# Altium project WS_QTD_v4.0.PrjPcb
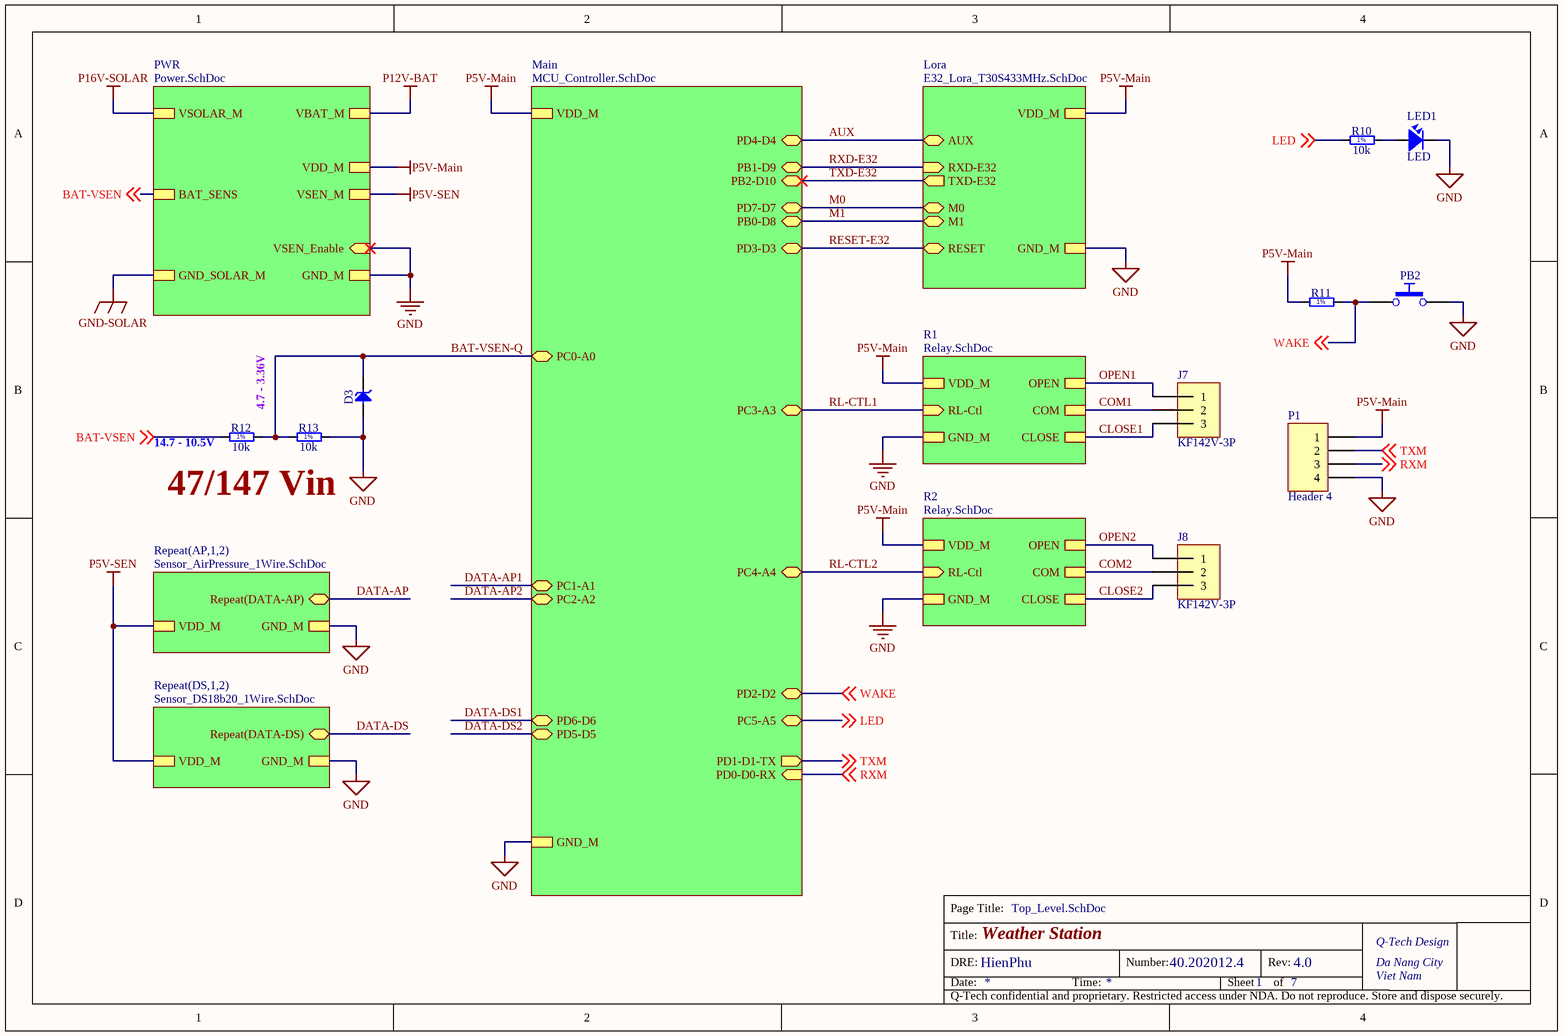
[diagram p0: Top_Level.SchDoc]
DocNumber: 40.202012.4; DRE: HienPhu; ProjectParameterName: Weather Station; Rev: 4.0
7 sheets, 75 parts. Net scope: strictly hierarchical (ports join the sheet entries above them; power ports are local).
Board file: Pcb_WS_v4.PcbDoc
Sheets:
  Top_Level.SchDoc
    Main = MCU_Controller.SchDoc
    Lora = E32_Lora_T30S433MHz.SchDoc
    PWR = Power.SchDoc
    AP1 = Sensor_AirPressure_1Wire.SchDoc
    AP2 = Sensor_AirPressure_1Wire.SchDoc
    DS1 = Sensor_DS18b20_1Wire.SchDoc
    DS2 = Sensor_DS18b20_1Wire.SchDoc
    R1 = Relay.SchDoc
    R2 = Relay.SchDoc

## Sheet Top_Level.SchDoc
size A4; Organization: Q-Tech Design; Address1: Da Nang City; Address2: Viet Nam; DocumentNumber: 1; SheetNumber: 1; SheetTotal: 7

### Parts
D3  BZV55-B5V1  [DIOMELF3515N]  (value not drawn)
J7  KF142V-3P  [CON KF142V-3P-5.08]
J8  KF142V-3P  [CON KF142V-3P-5.08]
LED1  LED  [L-0805]
P1  Header 4  [HDR1X4]
PB2  Push Button  [PB_TYCO_FSMSM]  (value not drawn)
R10  10k  [RESC1608X55N]
R11  10k  [RESC1608X55N]  (value not drawn)
R12  10k  [RESC1608X55N]
R13  10k  [RESC1608X55N]

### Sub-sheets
Lora = E32_Lora_T30S433MHz.SchDoc: M0 (bidir), M1 (bidir), RESET (bidir), AUX (bidir), GND_M, VDD_M, RXD-E32 (in), TXD-E32 (out)
Main = MCU_Controller.SchDoc: PB1-D9 (bidir), PB2-D10 (bidir), GND_M, PC3-A3 (bidir), PB0-D8 (bidir), PD6-D6 (bidir), PD2-D2 (bidir), PC4-A4 (bidir), PD4-D4 (bidir), PC5-A5 (bidir), PC2-A2 (bidir), PD0-D0-RX (in), PD3-D3 (bidir), PC1-A1 (bidir), PD7-D7 (bidir), VDD_M, PD5-D5 (bidir), PC0-A0 (bidir), PD1-D1-TX (out)
PWR = Power.SchDoc: VSOLAR_M, VSEN_Enable (in), BAT_SENS, VSEN_M, GND_SOLAR_M, VBAT_M, GND_M, VDD_M
R1 = Relay.SchDoc: OPEN, GND_M, CLOSE, RL-Ctl (in), VDD_M, COM
R2 = Relay.SchDoc: OPEN, GND_M, CLOSE, RL-Ctl (in), VDD_M, COM
Repeat(AP,1,2) = Sensor_AirPressure_1Wire.SchDoc: VDD_M, GND_M, Repeat(DATA-AP) (bidir)
Repeat(DS,1,2) = Sensor_DS18b20_1Wire.SchDoc: GND_M, Repeat(DATA-DS) (bidir), VDD_M

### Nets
GND: D3.2(A) LED1.2 P1.4 PB2.2 R13.2 ; sheet Main/GND_M, sheet Lora/GND_M, sheet PWR/VSEN_Enable, sheet PWR/GND_M, sheet Repeat(AP,1,2)/GND_M, sheet Repeat(DS,1,2)/GND_M, sheet R1/GND_M, sheet R2/GND_M
P5V-Main: P1.1 R11.1 ; sheet Main/VDD_M, sheet Lora/VDD_M, sheet PWR/VDD_M, sheet R1/VDD_M, sheet R2/VDD_M
P5V-SEN: sheet PWR/VSEN_M, sheet Repeat(AP,1,2)/VDD_M, sheet Repeat(DS,1,2)/VDD_M
AUX: sheet Main/PD4-D4, sheet Lora/AUX
BAT-VSEN: R12.1 ; off-sheet BAT-VSEN, sheet PWR/BAT_SENS
BAT-VSEN-Q: D3.1(C) R12.2 R13.1 ; sheet Main/PC0-A0
CLOSE1: J7.3 ; sheet R1/CLOSE
CLOSE2: J8.3 ; sheet R2/CLOSE
COM1: J7.2 ; sheet R1/COM
COM2: J8.2 ; sheet R2/COM
LED: R10.1 ; off-sheet LED, sheet Main/PC5-A5
M0: sheet Main/PD7-D7, sheet Lora/M0
M1: sheet Main/PB0-D8, sheet Lora/M1
OPEN1: J7.1 ; sheet R1/OPEN
OPEN2: J8.1 ; sheet R2/OPEN
RESET-E32: sheet Main/PD3-D3, sheet Lora/RESET
RL-CTL1: sheet Main/PC3-A3, sheet R1/RL-Ctl
RL-CTL2: sheet Main/PC4-A4, sheet R2/RL-Ctl
RXD-E32: sheet Main/PB1-D9, sheet Lora/RXD-E32
RXM: P1.3 ; off-sheet RXM, sheet Main/PD0-D0-RX
TXD-E32: sheet Main/PB2-D10, sheet Lora/TXD-E32
TXM: P1.2 ; off-sheet TXM, sheet Main/PD1-D1-TX
WAKE: PB2.1 R11.2 ; off-sheet WAKE, sheet Main/PD2-D2
NetLED1_1: LED1.1 R10.2

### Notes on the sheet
- (near R12) 14.7 - 10.5V
- 4.7 - 3.36V
- 47/147 Vin

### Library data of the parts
D3 = BZV55-B5V1: Zener Diode; Part Description: Voltage Regulator Diode; Manufacturer: NXP SEMICONDUCTORS; Voltage: 5V1; Power: 500mW; Table: Diodes
J7 J8 = CON KF142V-3P-5.08
LED1 = LED: LED Single colour Green and Red; Value: LED 3 ly Single Colour
P1 = Header 4: Header, 4-Pin
PB2 = PB SPST 1NO-2NO: Push-Button Switch SPDT; Part Description: 12VDC 50mA SPST Tactile  Push-Button Switch; Manufacturer: TYCO ELECTRONICS; Manufacturer Part Number: FSMSM or 1437566-3; Table: Switches
R10 = R0603_200R_1%_0.1W_100PPM: Resistor - 1%; Part Description: General Purpose Thick Film Chip Resistor; Manufacturer: GENERIC; Manufacturer1 Part Number: NRC06F2000TRF; Value: 200; Power: 0.1W; TC: ±100ppm/°C; Table: Resistors SMD
R11 = R0603_10K_1%_0.1W_100PPM: Resistor - 1%; Part Description: General Purpose Thick Film Chip Resistor; Manufacturer: GENERIC; Manufacturer1 Part Number: NRC06F1002TRF; Power: 0.1W; TC: ±100ppm/°C; Table: Resistors SMD
R12 = R0603_2M_1%_0.1W_100PPM: Resistor - 1%; Part Description: General Purpose Thick Film Chip Resistor; Manufacturer: GENERIC; Manufacturer1 Part Number: NRC06F2004TRF; Value: 2M; Power: 0.1W; TC: ±100ppm/°C; Table: Resistors SMD
R13 = R0603_1M_1%_0.1W_100PPM: Resistor - 1%; Part Description: General Purpose Thick Film Chip Resistor; Manufacturer: GENERIC; Manufacturer1 Part Number: NRC06F1004TRF; Value: 1M; Power: 0.1W; TC: ±100ppm/°C; Table: Resistors SMD

## Sheet MCU_Controller.SchDoc
size A4; Organization: Q-Tech Design; Address1: Da Nang City; Address2: Viet Nam; DocumentNumber: 2; SheetNumber: 2; SheetTotal: 7
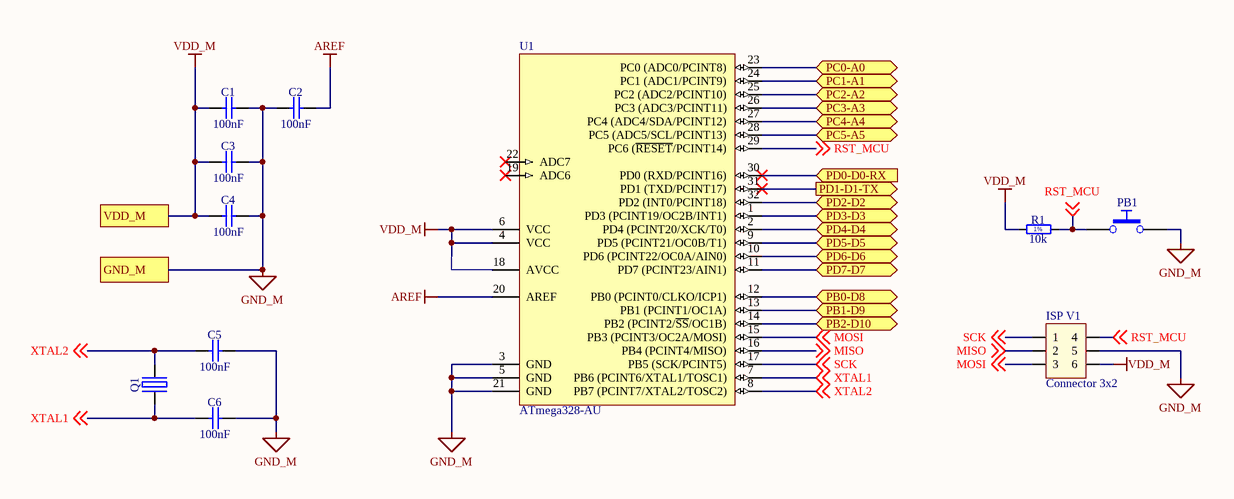
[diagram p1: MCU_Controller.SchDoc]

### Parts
C1  100nF  [CAPC1608X87N]
C2  100nF  [CAPC1608X87N]
C3  100nF  [CAPC1608X87N]
C4  100nF  [CAPC1608X87N]
C5  100nF  [CAPC1608X87N]
C6  100nF  [CAPC1608X87N]
ISP_V1  Connector 3x2  [JP3x2]
PB1  Push Button  [PB_TYCO_FSMSM]  (value not drawn)
Q1  20MHz  [XTAL_HC-49/U]  (value not drawn)
R1  10k  [RESC1608X55N]
U1  ATmega328-AU  [32A_ATM-M]

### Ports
GND_M, PB0-D8 (bidir), PB1-D9 (bidir), PB2-D10 (bidir), PC0-A0 (bidir), PC1-A1 (bidir), PC2-A2 (bidir), PC3-A3 (bidir), PC4-A4 (bidir), PC5-A5 (bidir), PD0-D0-RX (in), PD1-D1-TX (out), PD2-D2 (bidir), PD3-D3 (bidir), PD4-D4 (bidir), PD5-D5 (bidir), PD6-D6 (bidir), PD7-D7 (bidir), VDD_M

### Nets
AREF: C2.2 U1.20(AREF)
GND_M: C1.2 C2.1 C3.2 C4.2 C5.2 C6.2 ISP_V1.5 PB1.2 U1.3(GND) U1.5(GND) U1.21(GND) ; port GND_M  [project net GND]
VDD_M: C1.1 C3.1 C4.1 ISP_V1.6 R1.1 U1.4(VCC) U1.6(VCC) U1.18(AVCC) ; port VDD_M  [project net P5V-Main]
AUX: U1.2(PD4_(PCINT20/XCK/T0)) ; port PD4-D4
BAT-VSEN-Q: U1.23(PC0_(ADC0/PCINT8)) ; port PC0-A0
DATA-AP1: U1.24(PC1_(ADC1/PCINT9)) ; port PC1-A1
DATA-AP2: U1.25(PC2_(ADC2/PCINT10)) ; port PC2-A2
DATA-DS1: U1.10(PD6_(PCINT22/OC0A/AIN0)) ; port PD6-D6
DATA-DS2: U1.9(PD5_(PCINT21/OC0B/T1)) ; port PD5-D5
LED: U1.28(PC5_(ADC5/SCL/PCINT13)) ; port PC5-A5
M0: U1.11(PD7_(PCINT23/AIN1)) ; port PD7-D7
M1: U1.12(PB0_(PCINT0/CLKO/ICP1)) ; port PB0-D8
MISO: ISP_V1.2 U1.16(PB4_(PCINT4/MISO)) ; off-sheet MISO
MOSI: ISP_V1.3 U1.15(PB3_(PCINT3/OC2A/MOSI)) ; off-sheet MOSI
RESET-E32: U1.1(PD3_(PCINT19/OC2B/INT1)) ; port PD3-D3
RL-CTL1: U1.26(PC3_(ADC3/PCINT11)) ; port PC3-A3
RL-CTL2: U1.27(PC4_(ADC4/SDA/PCINT12)) ; port PC4-A4
RST_MCU: ISP_V1.4 PB1.1 R1.2 U1.29(PC6_(~{RESET}/PCINT14)) ; off-sheet RST_MCU
RXD-E32: U1.13(PB1_(PCINT1/OC1A)) ; port PB1-D9
RXM: U1.30(PD0_(RXD/PCINT16)) ; port PD0-D0-RX
SCK: ISP_V1.1 U1.17(PB5_(SCK/PCINT5)) ; off-sheet SCK
TXD-E32: U1.14(PB2_(PCINT2/~{SS}/OC1B)) ; port PB2-D10
TXM: U1.31(PD1_(TXD/PCINT17)) ; port PD1-D1-TX
WAKE: U1.32(PD2_(INT0/PCINT18)) ; port PD2-D2
XTAL1: C6.1 Q1.1(OSC1) U1.7(PB6_(PCINT6/XTAL1/TOSC1)) ; off-sheet XTAL1
XTAL2: C5.1 Q1.2(OSC2) U1.8(PB7_(PCINT7/XTAL2/TOSC2)) ; off-sheet XTAL2

Not connected (* = marked no-connect by the designer): U1 19(ADC6)* 22(ADC7)*

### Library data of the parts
C1-C4 = CC0603_100NF_50V_10%_X7R: Non-polarised capacitor; Part Description: SMD Multilayer Chip Ceramic Capacitor; Manufacturer: GENERIC; Manufacturer1 Part Number: 223858615649; Voltage: 50V; TC: X7R; Tolerance: ±10%; Table: Capacitors SMD
C5 C6 = CC0603_22PF_50V_5%_NP0: Non-polarised capacitor; Part Description: SMD Multilayer Chip Ceramic Capacitor; Manufacturer: GENERIC; Manufacturer1 Part Number: 223886715229; Value: 22pF; Voltage: 50V; TC: NP0; Tolerance: ±5%; Table: Capacitors SMD
ISP_V1 = JP3x2
PB1 = PB SPST 1NO-2NO: as PB2 on sheet Top_Level
Q1 = XTAL_20MHZ_AEL_HC-49/U: Quartz Crystal; Part Description: ±30ppm Quartz Crystal Resonator, HC-49/U Type; Manufacturer: AEL CRYSTALS; Manufacturer Part Number: X20M000000L010; Table: Crystals & Oscillators
R1 = R0603_10K_1%_0.1W_100PPM: as R11 on sheet Top_Level
U1 = ATmega328-AU: 8-bit AVR Microcontroller, 32KB Flash, 1KB EEPROM, 2KB SRAM, 32-pin TQFP, Industrial Grade (-40°C to 85°C)

## Sheet E32_Lora_T30S433MHz.SchDoc
size A4; Organization: Q-Tech Design; Address1: Da Nang City; Address2: Viet Nam; DocumentNumber: 3; SheetNumber: 3; SheetTotal: 7
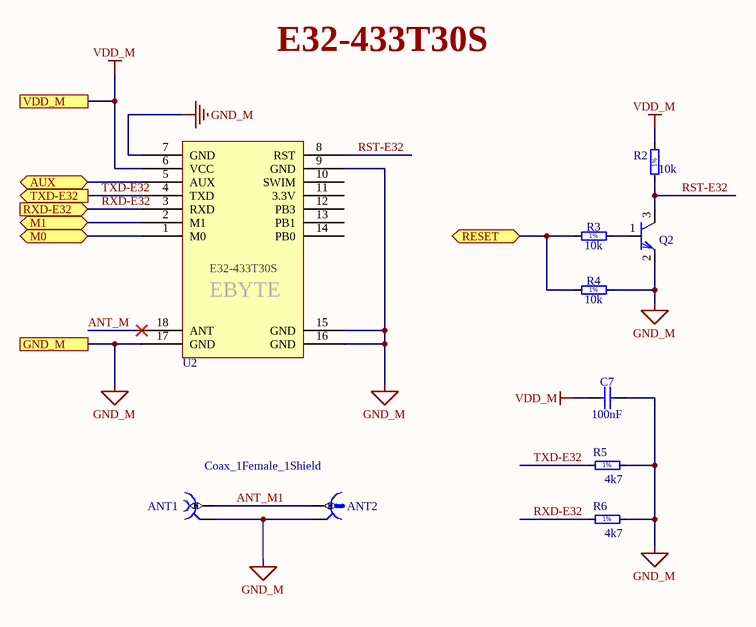
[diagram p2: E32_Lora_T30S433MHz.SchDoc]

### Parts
ANT1  Coax_1Female_1Shield  [HUBER-SUHNER_85 SMA-50-0-101/111 NE]
ANT2  U.FL  [HIROSE_U.FL-R-SMT-1(10)]  (value not drawn)
C7  100nF  [CAPC1608X87N]
Q2  C1815  [SOT23-3]  (value not drawn)
R2  10k  [RESC1608X55N]
R3  10k  [RESC1608X55N]
R4  10k  [RESC1608X55N]
R5  4k7  [RESC1608X55N]
R6  4k7  [RESC1608X55N]
U2  E32-T30S  [E32-T30S]  (value not drawn)

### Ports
AUX (bidir), GND_M, M0 (bidir), M1 (bidir), RESET (bidir), RXD-E32 (in), TXD-E32 (out), VDD_M

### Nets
GND_M: ANT1.2 ANT2.2 C7.2 Q2.2(E) R4.1 R5.2 R6.2 U2.7(GND) U2.9(GND) U2.15(GND) U2.16(GND) U2.17(GND) ; port GND_M  [project net GND]
VDD_M: C7.1 R2.2 U2.6(VCC) ; port VDD_M  [project net P5V-Main]
ANT_M: U2.18(ANT)
ANT_M1: ANT1.1 ANT2.1
AUX: U2.5(AUX) ; port AUX
M0: U2.1(M0) ; port M0
M1: U2.2(M1) ; port M1
RESET-E32: R3.1 R4.2 ; port RESET
RST-E32: Q2.3(C) R2.1 U2.8(RST)
RXD-E32: R6.1 U2.3(RXD) ; port RXD-E32
TXD-E32: R5.1 U2.4(TXD) ; port TXD-E32
NetQ2_1: Q2.1(B) R3.2

Not connected (* = marked no-connect by the designer): U2 10(SWIM) 11(3.3V) 12(PB3) 13(PB1) 14(PB0)

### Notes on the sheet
- E32-433T30S

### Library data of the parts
ANT1 = HUBER-SUHNER_85_SMA-50-0-101/111_NE: Part Description: SMA 50 Ohms Right Angle PCB Jack; Manufacturer: HUBER+SUHNER; Table: Miscellaneous
ANT2 = HIROSE_U.FL-R-SMT-1(10): Part Description: Up to 6GHz Ultra Small Surface Mount Male Coaxial Connectors U.FL Series; Manufacturer: HIROSE (HRS); Table: Miscellaneous
C7 = CC0603_100NF_50V_10%_X7R: as C1 on sheet MCU_Controller
Q2 = 2SC1815: PSpiceTemplate: Q^@REFDES %c %b %e @MODEL; Vendor: Digikey
R2 = R0603_4K7_1%_0.1W_100PPM: Resistor - 1%; Part Description: General Purpose Thick Film Chip Resistor; Manufacturer: GENERIC; Manufacturer1 Part Number: NRC06F4701TRF; Value: 4k7; Power: 0.1W; TC: ±100ppm/°C; Table: Resistors SMD
R3 R4 = R0603_1K_1%_0.1W_100PPM: Resistor - 1%; Part Description: General Purpose Thick Film Chip Resistor; Manufacturer: GENERIC; Manufacturer1 Part Number: NRC06F1001TRF; Value: 1k; Power: 0.1W; TC: ±100ppm/°C; Table: Resistors SMD
R5 R6 = R0603_10K_1%_0.1W_100PPM: Resistor - 1%; Part Description: General Purpose Thick Film Chip Resistor; Manufacturer: GENERIC; Manufacturer1 Part Number: NRC06F1002TRF; Value: 10k; Power: 0.1W; TC: ±100ppm/°C; Table: Resistors SMD
U2 = E32-433T30S: Lora Ebyte E32-T30S Module

## Sheet Power.SchDoc
size A4; Organization: Q-Tech Design; Address1: Da Nang City; Address2: Viet Nam; DocumentNumber: 7; SheetNumber: 7; SheetTotal: 7
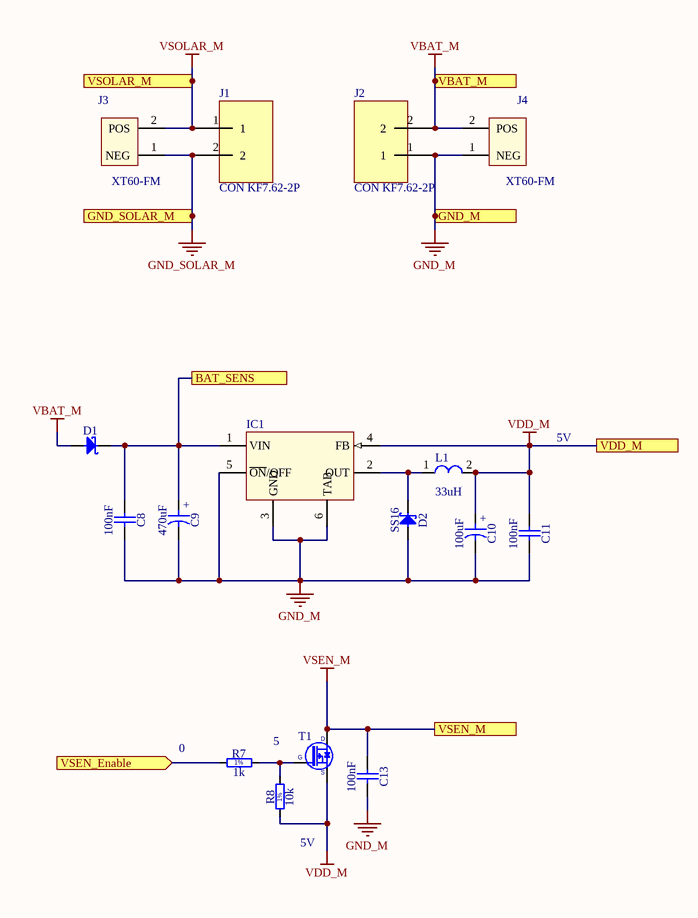
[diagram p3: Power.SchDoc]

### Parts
C8  100nF  [CAPC1608X87N]
C9  470uF  [CAPAE1030X1020N]
C10  100uF  [CAPMP6032X280N]
C11  100nF  [CAPC1608X87N]
C13  100nF  [CAPC1608X87N]
D1  SS16  [DIOM5127X229N]  (value not drawn)
D2  SS16  [DIOM5127X229N]
IC1  LM2596  [TO263-5]  (value not drawn)
J1  CON KF7.62-2P  [CON KF7.62-2P]
J2  CON KF7.62-2P  [CON KF7.62-2P]
J3  XT60-FM  [XT60-FM]
J4  XT60-FM  [XT60-FM]
L1  33uH  [L_SMD]
R7  1k  [RESC1608X55N]
R8  10k  [RESC1608X55N]
T1  BSH203  [SOT95P230X110-3N]  (value not drawn)

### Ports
BAT_SENS, GND_M, GND_SOLAR_M, VBAT_M, VDD_M, VSEN_Enable (in), VSEN_M, VSOLAR_M

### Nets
GND_M: C8.2 C9.2 C10.2 C11.2 C13.2 D2.2(A) IC1.3(GND) IC1.5(~{ON}/OFF) IC1.6(TAB) J2.1 J4.1(NEG) R7.1 ; port GND_M, port VSEN_Enable  [project net GND]
GND_SOLAR_M: J1.2 J3.1(NEG) ; port GND_SOLAR_M  [project net GND-SOLAR]
VBAT_M: D1.2(A) J2.2 J4.2(POS) ; port VBAT_M  [project net P12V-BAT]
VDD_M: C10.1 C11.1 IC1.4(FB) L1.2 R8.1 T1.2(S) ; port VDD_M  [project net P5V-Main]
VSEN_M: C13.1 T1.3(D) ; port VSEN_M  [project net P5V-SEN]
VSOLAR_M: J1.1 J3.2(POS) ; port VSOLAR_M  [project net P16V-SOLAR]
BAT-VSEN: C8.1 C9.1 D1.1(C) IC1.1(VIN) ; port BAT_SENS
NetD2_1: D2.1(C) IC1.2(OUT) L1.1
NetR7_2: R7.2 R8.2 T1.1(G)

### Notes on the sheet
- 5V
- 5
- (near R7) 0
- (near R8) 5V

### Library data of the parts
C8 C11 C13 = CC0603_100NF_50V_10%_X7R: as C1 on sheet MCU_Controller
C9 = CAE1030-1020_470UF_25V_20%: Polarised capacitor; Part Description: Aluminum Electrolytic SMT Capacitor; Manufacturer: GENERIC; Manufacturer1 Part Number: EEEFK1E471AP; Voltage: 25V; Tolerance: ±20%; Table: Capacitors SMD
C10 = CTE6032-28_100UF_6.3V_10%_LESR0075: Polarised capacitor; Part Description: Low ESR 0R075 Solid Tantalum Chip Capacitor; Manufacturer: GENERIC; Manufacturer1 Part Number: TPSC107K006R0075; Voltage: 6.3V; Tolerance: ±10%; Table: Capacitors SMD
D1 D2 = SS16: Schottky Diode; Part Description: Surface Mount Schottky Barrier Rectifier; Manufacturer: VISHAY GENERAL SEMICONDUCTOR; Voltage: 60V; Power: 1A; Table: Diodes
IC1 = LM2596-5V
J3 J4 = XT60-FM: MF: AMASS; MP: XT60-M
L1 = L_SMD 33uH
R7 = R0603_1K_1%_0.1W_100PPM: Resistor - 1%; Part Description: General Purpose Thick Film Chip Resistor; Manufacturer: GENERIC; Manufacturer1 Part Number: NRC06F1001TRF; Power: 0.1W; TC: ±100ppm/°C; Table: Resistors SMD
R8 = R0603_10K_1%_0.1W_100PPM: as R11 on sheet Top_Level
T1 = BSH203: P-CHANNEL MOSFET WITH DIODE; Part Description: -30V -470mA P-Channel Enhancement Mode MOS Transistor; Manufacturer: NXP SEMICONDUCTORS; Table: Transistors

## Sheet Sensor_AirPressure_1Wire.SchDoc
size A4; Organization: Q-Tech Design; Address1: Da Nang City; Address2: Viet Nam; DocumentNumber: 4; SheetNumber: 4; SheetTotal: 7
Used 2 times, as channels AP1, AP2. Parts and nets are listed once, with the designators drawn on the sheet.
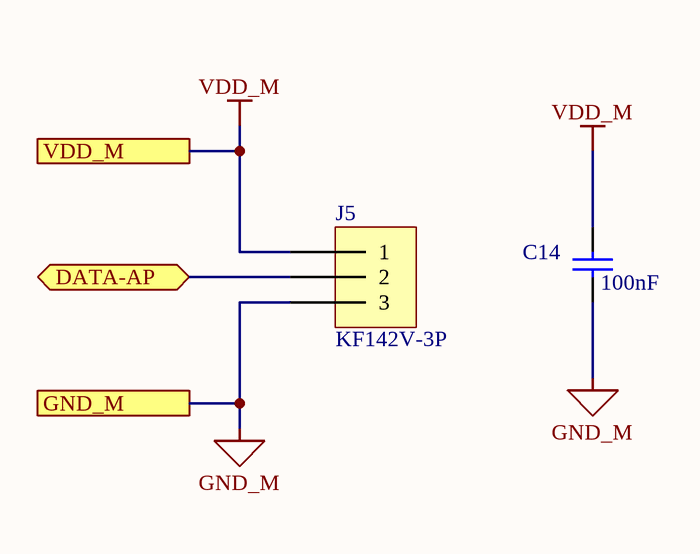
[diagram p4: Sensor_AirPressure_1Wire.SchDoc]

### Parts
C14  100nF  [CAPC1608X87N]
J5  KF142V-3P  [CON KF142V-3P-5.08]

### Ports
DATA-AP (bidir), GND_M, VDD_M

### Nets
GND_M: C14.1 J5.3 ; port GND_M
VDD_M: C14.2 J5.1 ; port VDD_M
DATA-AP: J5.2 ; port DATA-AP

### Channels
AP1: designators end in AP1; ports DATA-AP=DATA-AP1 GND_M=GND VDD_M=P5V-SEN
AP2: designators end in AP2; ports DATA-AP=DATA-AP2 GND_M=GND VDD_M=P5V-SEN

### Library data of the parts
C14 = CC0603_100NF_50V_10%_X7R: as C1 on sheet MCU_Controller
J5 = CON KF142V-3P-5.08

## Sheet Sensor_DS18b20_1Wire.SchDoc
size A4; Organization: Q-Tech Design; Address1: Da Nang City; Address2: Viet Nam; DocumentNumber: 5; SheetNumber: 5; SheetTotal: 7
Used 2 times, as channels DS1, DS2. Parts and nets are listed once, with the designators drawn on the sheet.
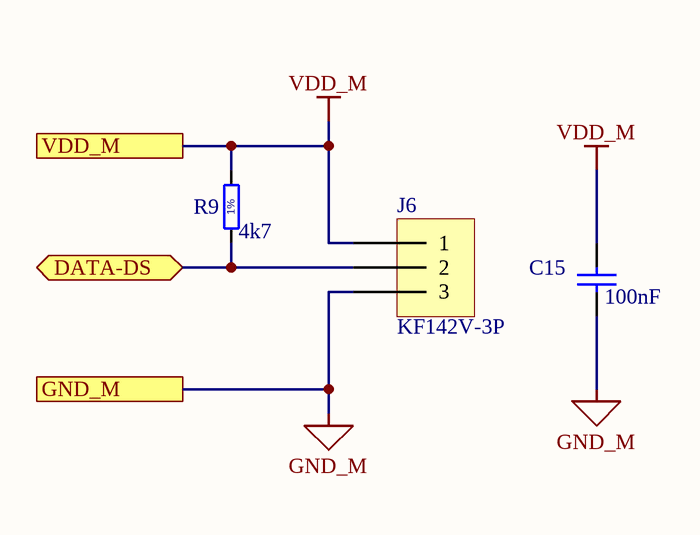
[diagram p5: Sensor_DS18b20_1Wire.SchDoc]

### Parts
C15  100nF  [CAPC1608X87N]
J6  KF142V-3P  [CON KF142V-3P-5.08]
R9  4k7  [RESC1608X55N]

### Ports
DATA-DS (bidir), GND_M, VDD_M

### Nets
GND_M: C15.1 J6.3 ; port GND_M
VDD_M: C15.2 J6.1 R9.2 ; port VDD_M
DATA-DS: J6.2 R9.1 ; port DATA-DS

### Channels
DS1: designators end in DS1; ports DATA-DS=DATA-DS1 GND_M=GND VDD_M=P5V-SEN
DS2: designators end in DS2; ports DATA-DS=DATA-DS2 GND_M=GND VDD_M=P5V-SEN

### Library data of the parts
C15 = CC0603_100NF_50V_10%_X7R: as C1 on sheet MCU_Controller
J6 = CON KF142V-3P-5.08
R9 = R0603_4K7_1%_0.1W_100PPM: Resistor - 1%; Part Description: General Purpose Thick Film Chip Resistor; Manufacturer: GENERIC; Manufacturer1 Part Number: NRC06F4701TRF; Power: 0.1W; TC: ±100ppm/°C; Table: Resistors SMD

## Sheet Relay.SchDoc
size A4; Organization: Q-Tech Design; Address1: Da Nang City; Address2: Viet Nam; DocumentNumber: 6; SheetNumber: 6; SheetTotal: 7
Used 2 times, as channels R1, R2. Parts and nets are listed once, with the designators drawn on the sheet.
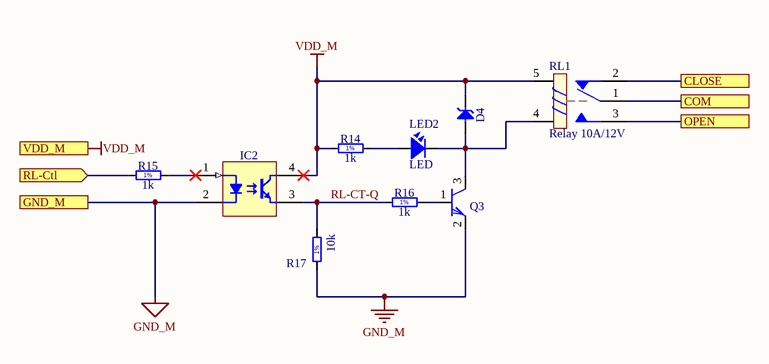
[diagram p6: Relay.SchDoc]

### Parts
D4  BZG03C220  [DIOM5326X230N]  (value not drawn)
IC2  SFH6156-4  [SOIC254P977X406-4N]  (value not drawn)
LED2  LED  [L-0805]
Q3  C1815  [SOT23-3]  (value not drawn)
R14  1k  [RESC1608X55N]
R15  1k  [RESC1608X55N]
R16  1k  [RESC1608X55N]
R17  10k  [RESC1608X55N]
RL1  Relay 10A/12V  [RL_SPDT_10A]

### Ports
CLOSE, COM, GND_M, OPEN, RL-Ctl (in), VDD_M

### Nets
GND_M: IC2.2(C) Q3.2(E) R17.1 ; port GND_M
VDD_M: D4.1(C) IC2.4(C) R14.1 RL1.5 ; port VDD_M
CLOSE: RL1.2 ; port CLOSE
COM: RL1.1 ; port COM
OPEN: RL1.3 ; port OPEN
RL-CT-Q: IC2.3(E) R16.1 R17.2
RL-Ctl: R15.1 ; port RL-Ctl
NetD4_2: D4.2(A) LED2.2 Q3.3(C) RL1.4
NetIC2_1: IC2.1(A) R15.2
NetLED2_1: LED2.1 R14.2
NetQ3_1: Q3.1(B) R16.2

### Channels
R1: designators end in R1; ports CLOSE=CLOSE1 COM=COM1 GND_M=GND OPEN=OPEN1 RL-Ctl=RL-CTL1 VDD_M=P5V-Main
R2: designators end in R2; ports CLOSE=CLOSE2 COM=COM2 GND_M=GND OPEN=OPEN2 RL-Ctl=RL-CTL2 VDD_M=P5V-Main

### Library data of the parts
D4 = BZG03C220: Zener Diode; Part Description: Voltage Regulator Diode; Manufacturer: VISHAY SEMICONDUCTOR; Voltage: 220V; Power: 1.25W; Table: Diodes
IC2 = SFH6156-4: Single Optocoupler; Part Description: Optocoupler, Phototransistor Output, High Reliability, 5300 VRMS; Manufacturer: VISHAY SEMICONDUCTORS; Table: Optocouplers
LED2 = LED: as LED1 on sheet Top_Level
Q3 = 2SC1815: as Q2 on sheet E32_Lora_T30S433MHz
R14 R16 = R0603_200R_1%_0.1W_100PPM: as R10 on sheet Top_Level
R15 = R0603_1K_1%_0.1W_100PPM: as R7 on sheet Power
R17 = R0603_10K_1%_0.1W_100PPM: as R11 on sheet Top_Level
RL1 = Relay 1: Relay SPDT,10A - 12VDC 5 Pin; Value: Relay SPDT, 10A, 12V

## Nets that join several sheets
GND: Top_Level (5 pins), MCU_Controller (11 pins), E32_Lora_T30S433MHz (12 pins), Power (12 pins), AP1 (C14AP1.1 J5AP1.3), AP2 (C14AP2.1 J5AP2.3), DS1 (C15DS1.1 J6DS1.3), DS2 (C15DS2.1 J6DS2.3), R1 (IC2R1.2 Q3R1.2 R17R1.1), R2 (IC2R2.2 Q3R2.2 R17R2.1)
P5V-Main: Top_Level (P1.1 R11.1), MCU_Controller (8 pins), E32_Lora_T30S433MHz (C7.1 R2.2 U2.6), Power (6 pins), R1 (D4R1.1 IC2R1.4 R14R1.1 RL1R1.5), R2 (D4R2.1 IC2R2.4 R14R2.1 RL1R2.5)
P5V-SEN: Power (C13.1 T1.3), AP1 (C14AP1.2 J5AP1.1), AP2 (C14AP2.2 J5AP2.1), DS1 (C15DS1.2 J6DS1.1 R9DS1.2), DS2 (C15DS2.2 J6DS2.1 R9DS2.2)
AUX: MCU_Controller (U1.2), E32_Lora_T30S433MHz (U2.5)
BAT-VSEN: Top_Level (R12.1), Power (C8.1 C9.1 D1.1 IC1.1)
BAT-VSEN-Q: Top_Level (D3.1 R12.2 R13.1), MCU_Controller (U1.23)
CLOSE1: Top_Level (J7.3), R1 (RL1R1.2)
CLOSE2: Top_Level (J8.3), R2 (RL1R2.2)
COM1: Top_Level (J7.2), R1 (RL1R1.1)
COM2: Top_Level (J8.2), R2 (RL1R2.1)
DATA-AP1: MCU_Controller (U1.24), AP1 (J5AP1.2)
DATA-AP2: MCU_Controller (U1.25), AP2 (J5AP2.2)
DATA-DS1: MCU_Controller (U1.10), DS1 (J6DS1.2 R9DS1.1)
DATA-DS2: MCU_Controller (U1.9), DS2 (J6DS2.2 R9DS2.1)
LED: Top_Level (R10.1), MCU_Controller (U1.28)
M0: MCU_Controller (U1.11), E32_Lora_T30S433MHz (U2.1)
M1: MCU_Controller (U1.12), E32_Lora_T30S433MHz (U2.2)
OPEN1: Top_Level (J7.1), R1 (RL1R1.3)
OPEN2: Top_Level (J8.1), R2 (RL1R2.3)
RESET-E32: MCU_Controller (U1.1), E32_Lora_T30S433MHz (R3.1 R4.2)
RL-CTL1: MCU_Controller (U1.26), R1 (R15R1.1)
RL-CTL2: MCU_Controller (U1.27), R2 (R15R2.1)
RXD-E32: MCU_Controller (U1.13), E32_Lora_T30S433MHz (R6.1 U2.3)
RXM: Top_Level (P1.3), MCU_Controller (U1.30)
TXD-E32: MCU_Controller (U1.14), E32_Lora_T30S433MHz (R5.1 U2.4)
TXM: Top_Level (P1.2), MCU_Controller (U1.31)
WAKE: Top_Level (PB2.1 R11.2), MCU_Controller (U1.32)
